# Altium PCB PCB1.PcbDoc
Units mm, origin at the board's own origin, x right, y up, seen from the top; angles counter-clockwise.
Board outline 55 x 52 mm, 6 copper layers (Top Layer, Int1 (GND), Int2 (Sign), Int3 (Sign), Int4 (PWR), Bottom Layer), stack 1.551 mm thick; 24 components, 14 nets, 48 pads, 20 vias.
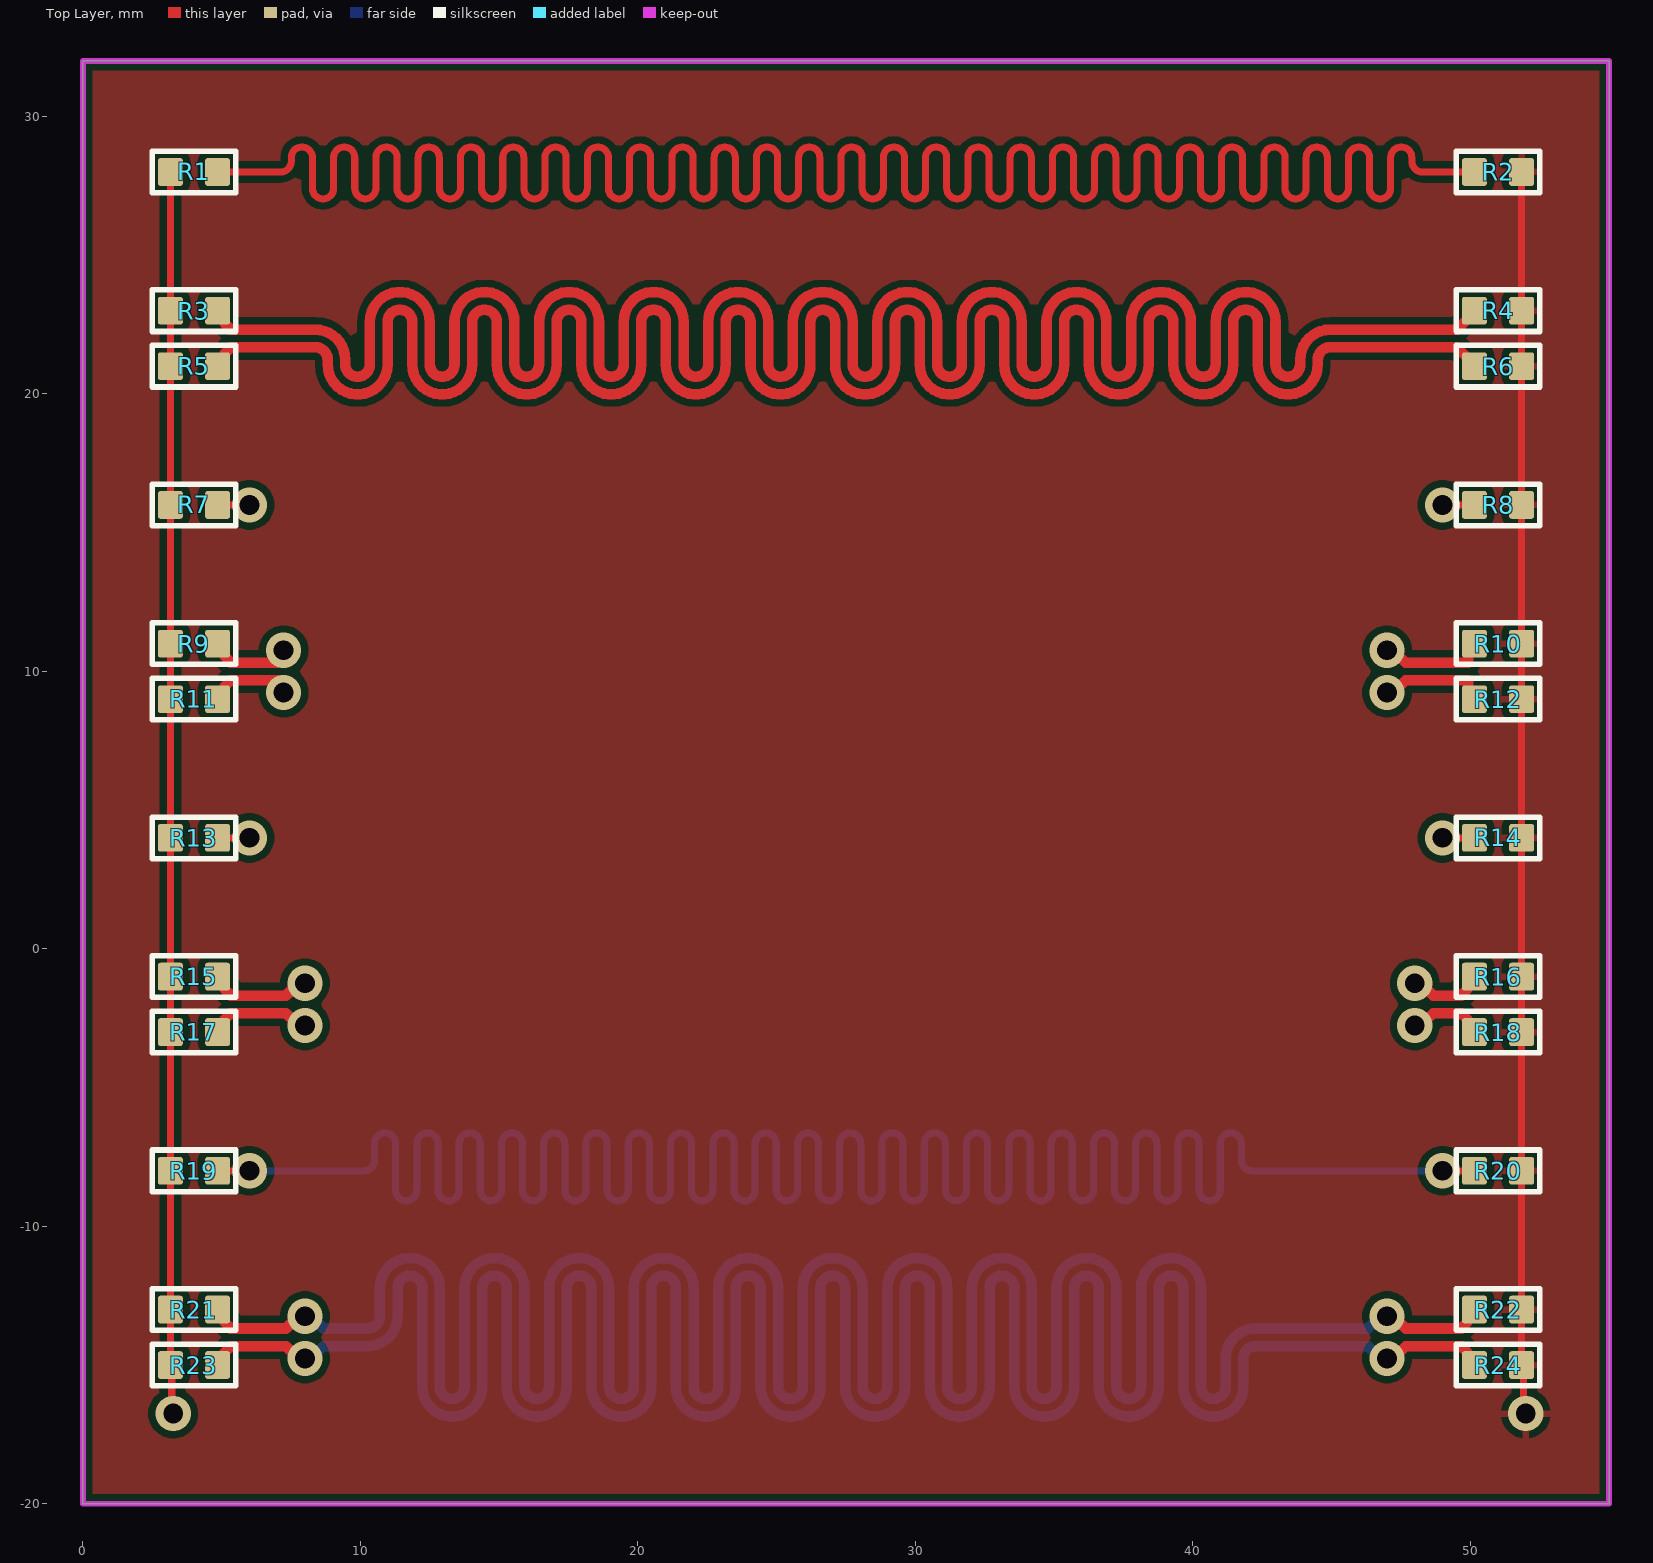
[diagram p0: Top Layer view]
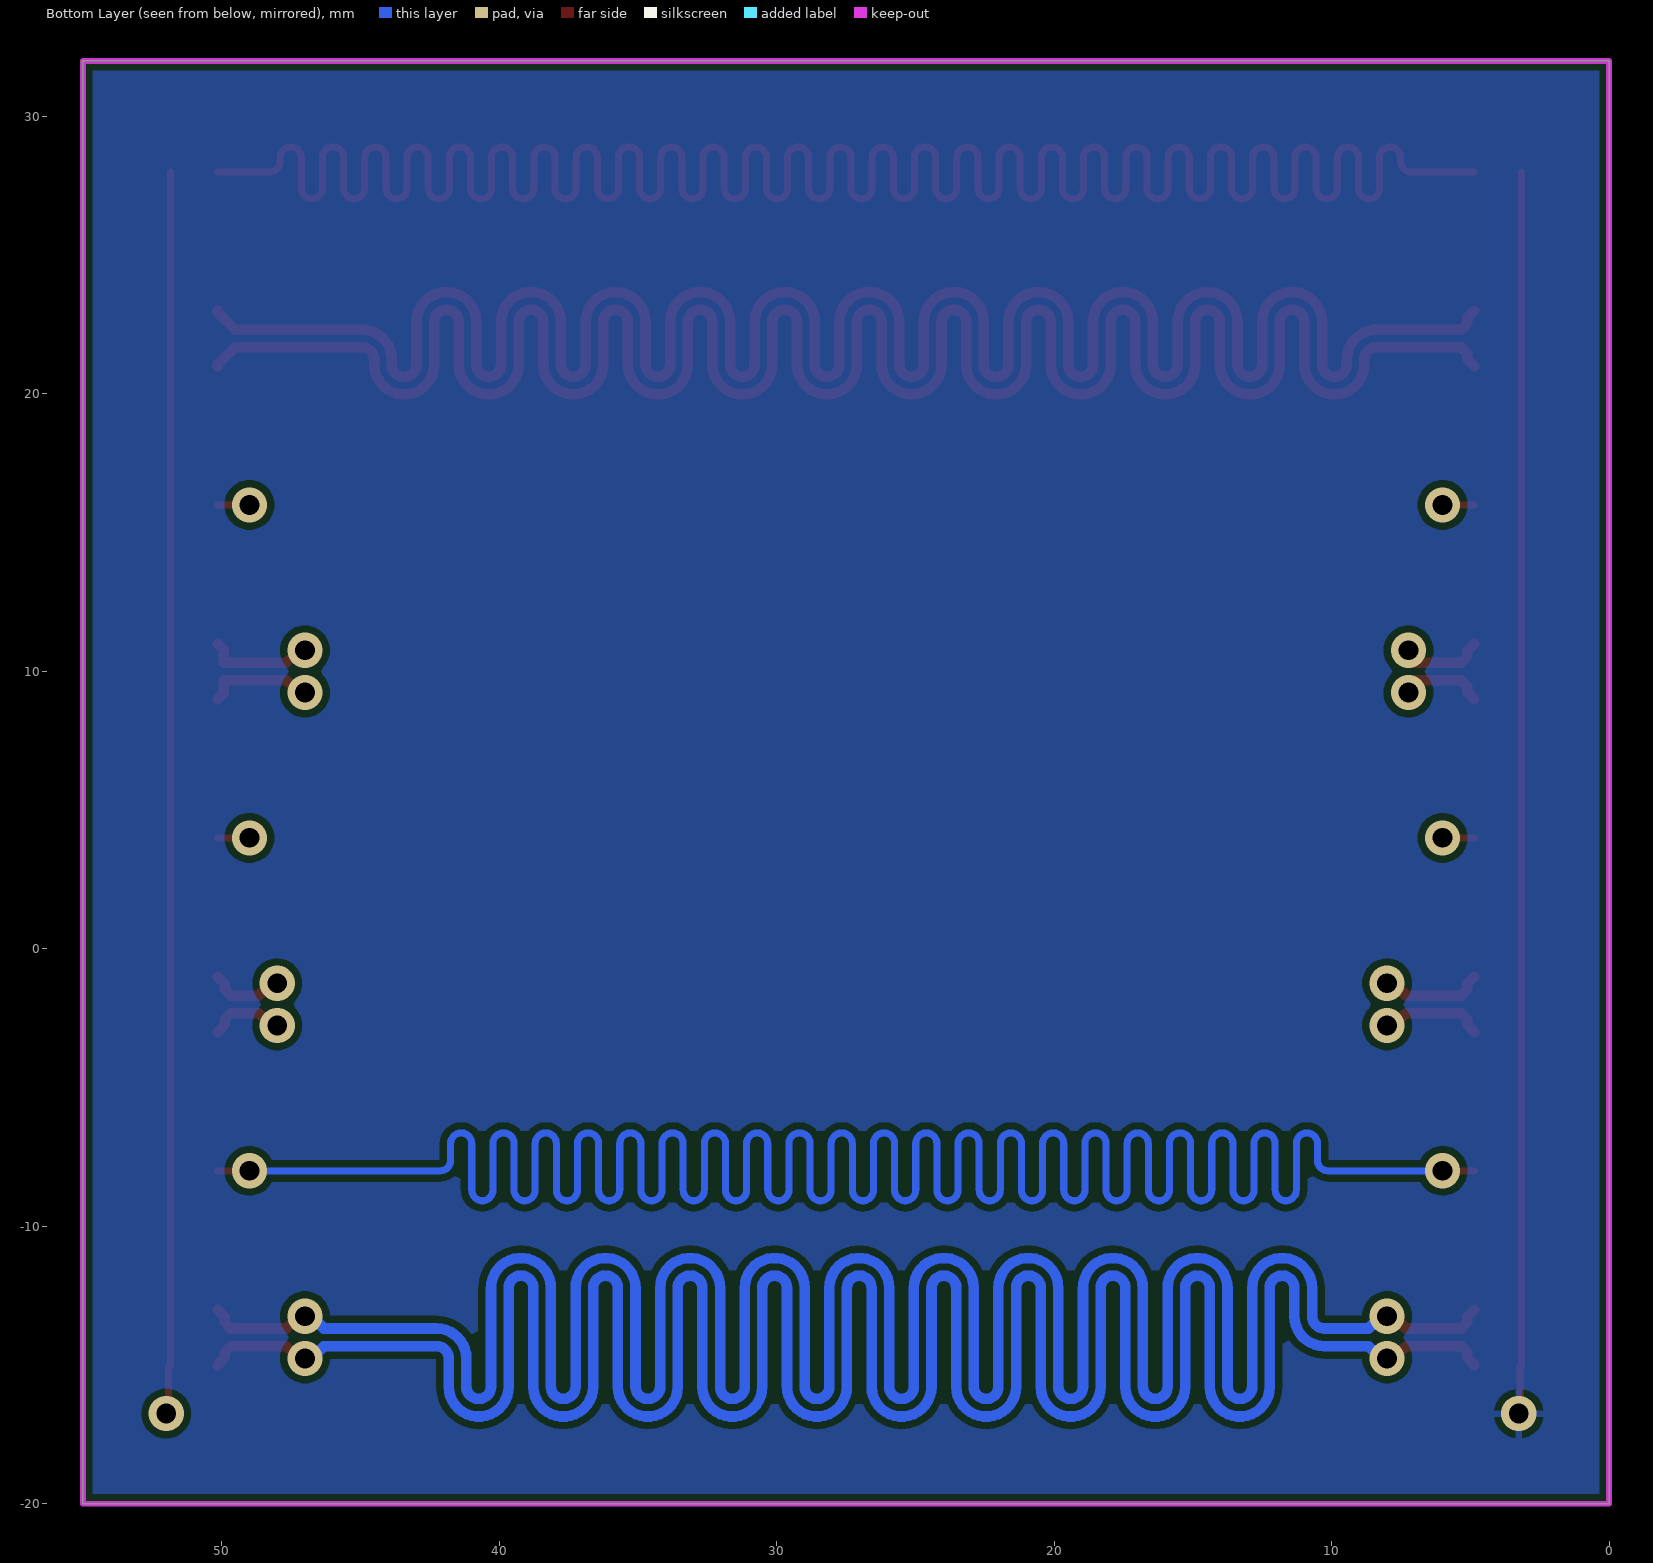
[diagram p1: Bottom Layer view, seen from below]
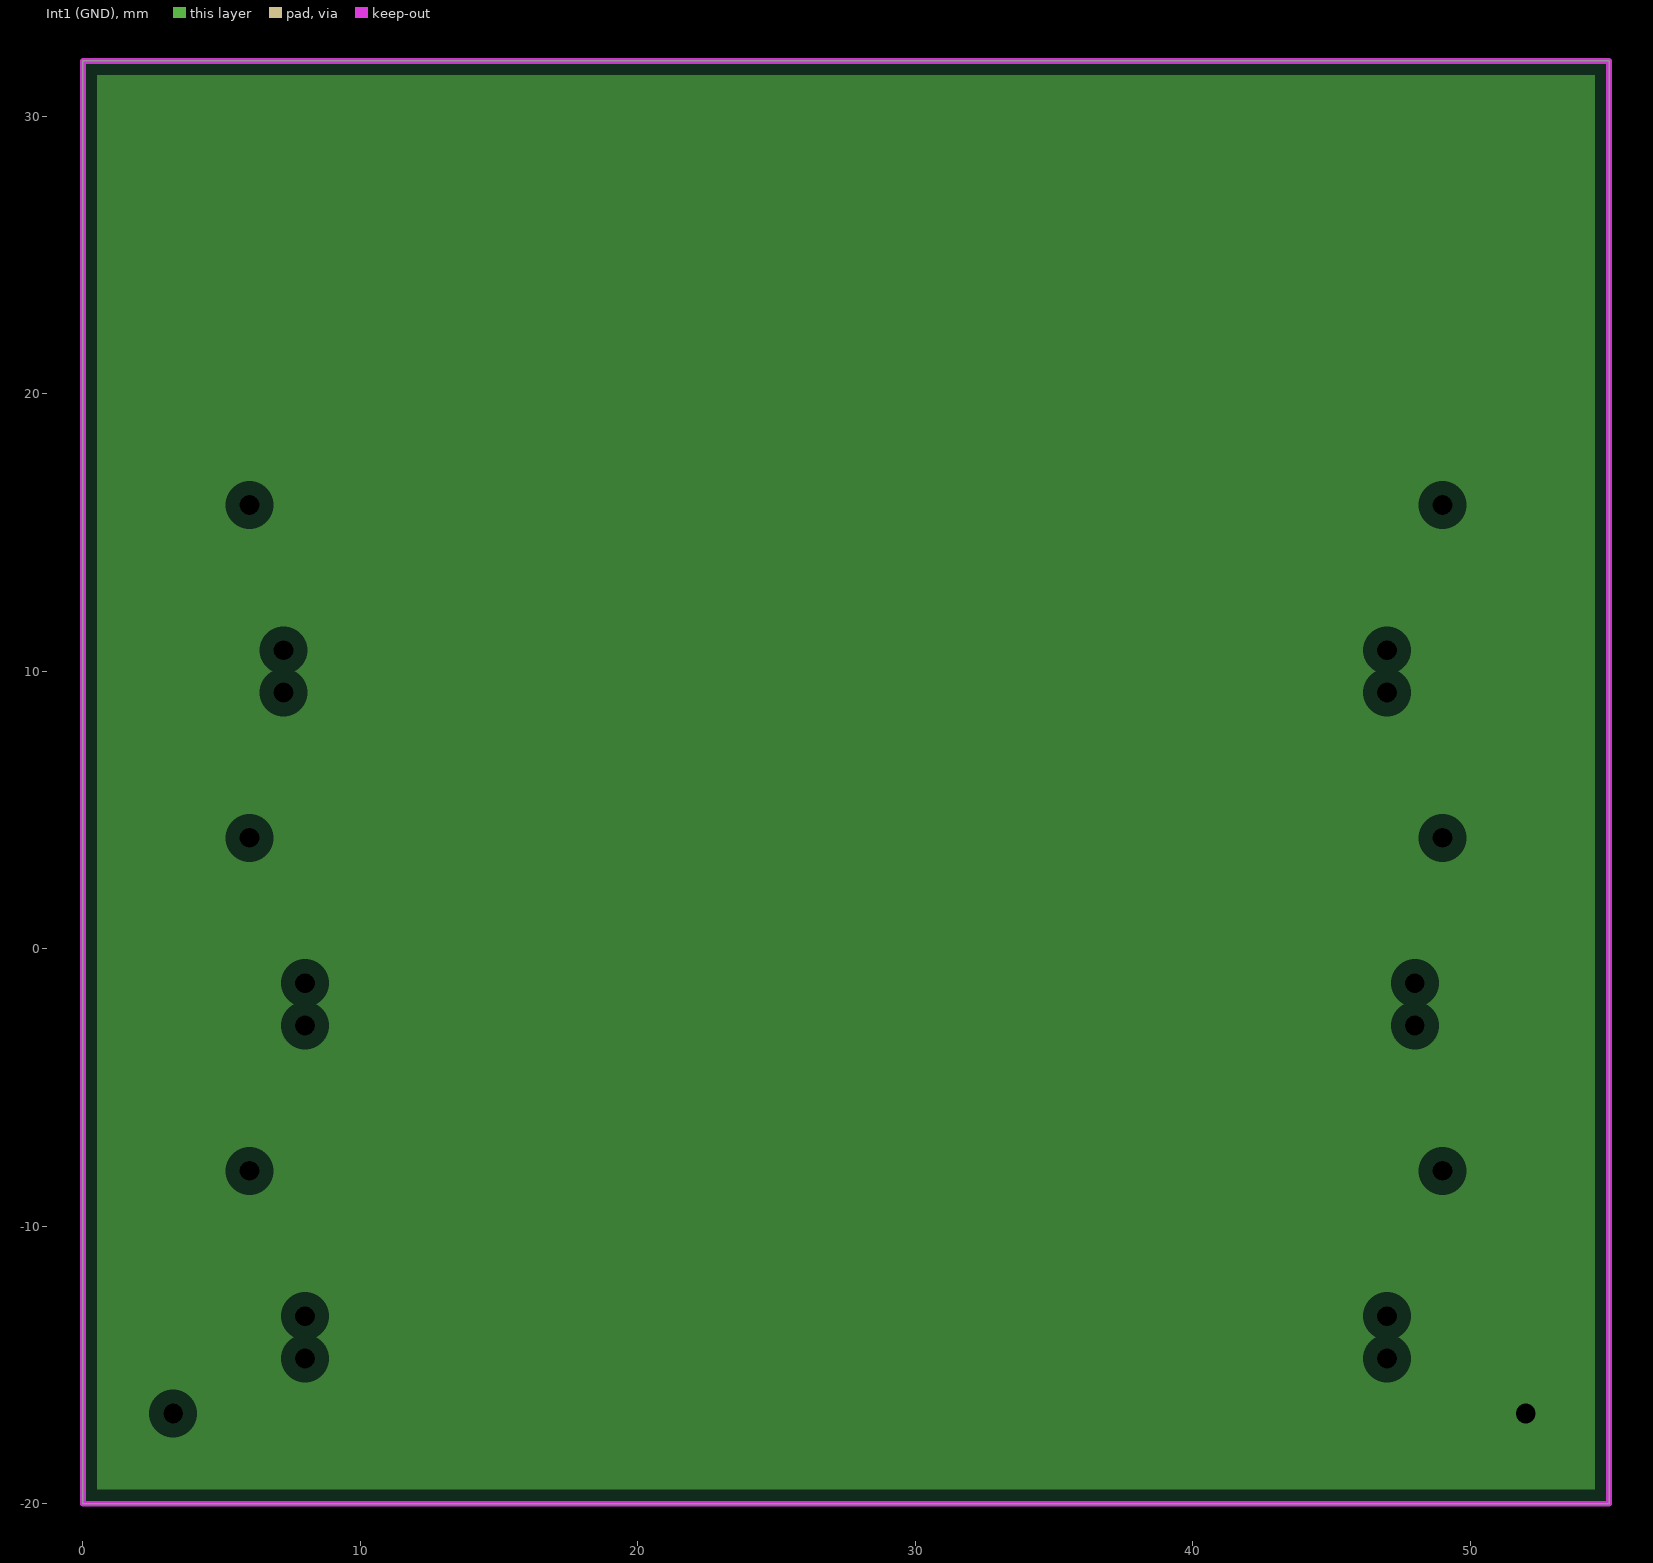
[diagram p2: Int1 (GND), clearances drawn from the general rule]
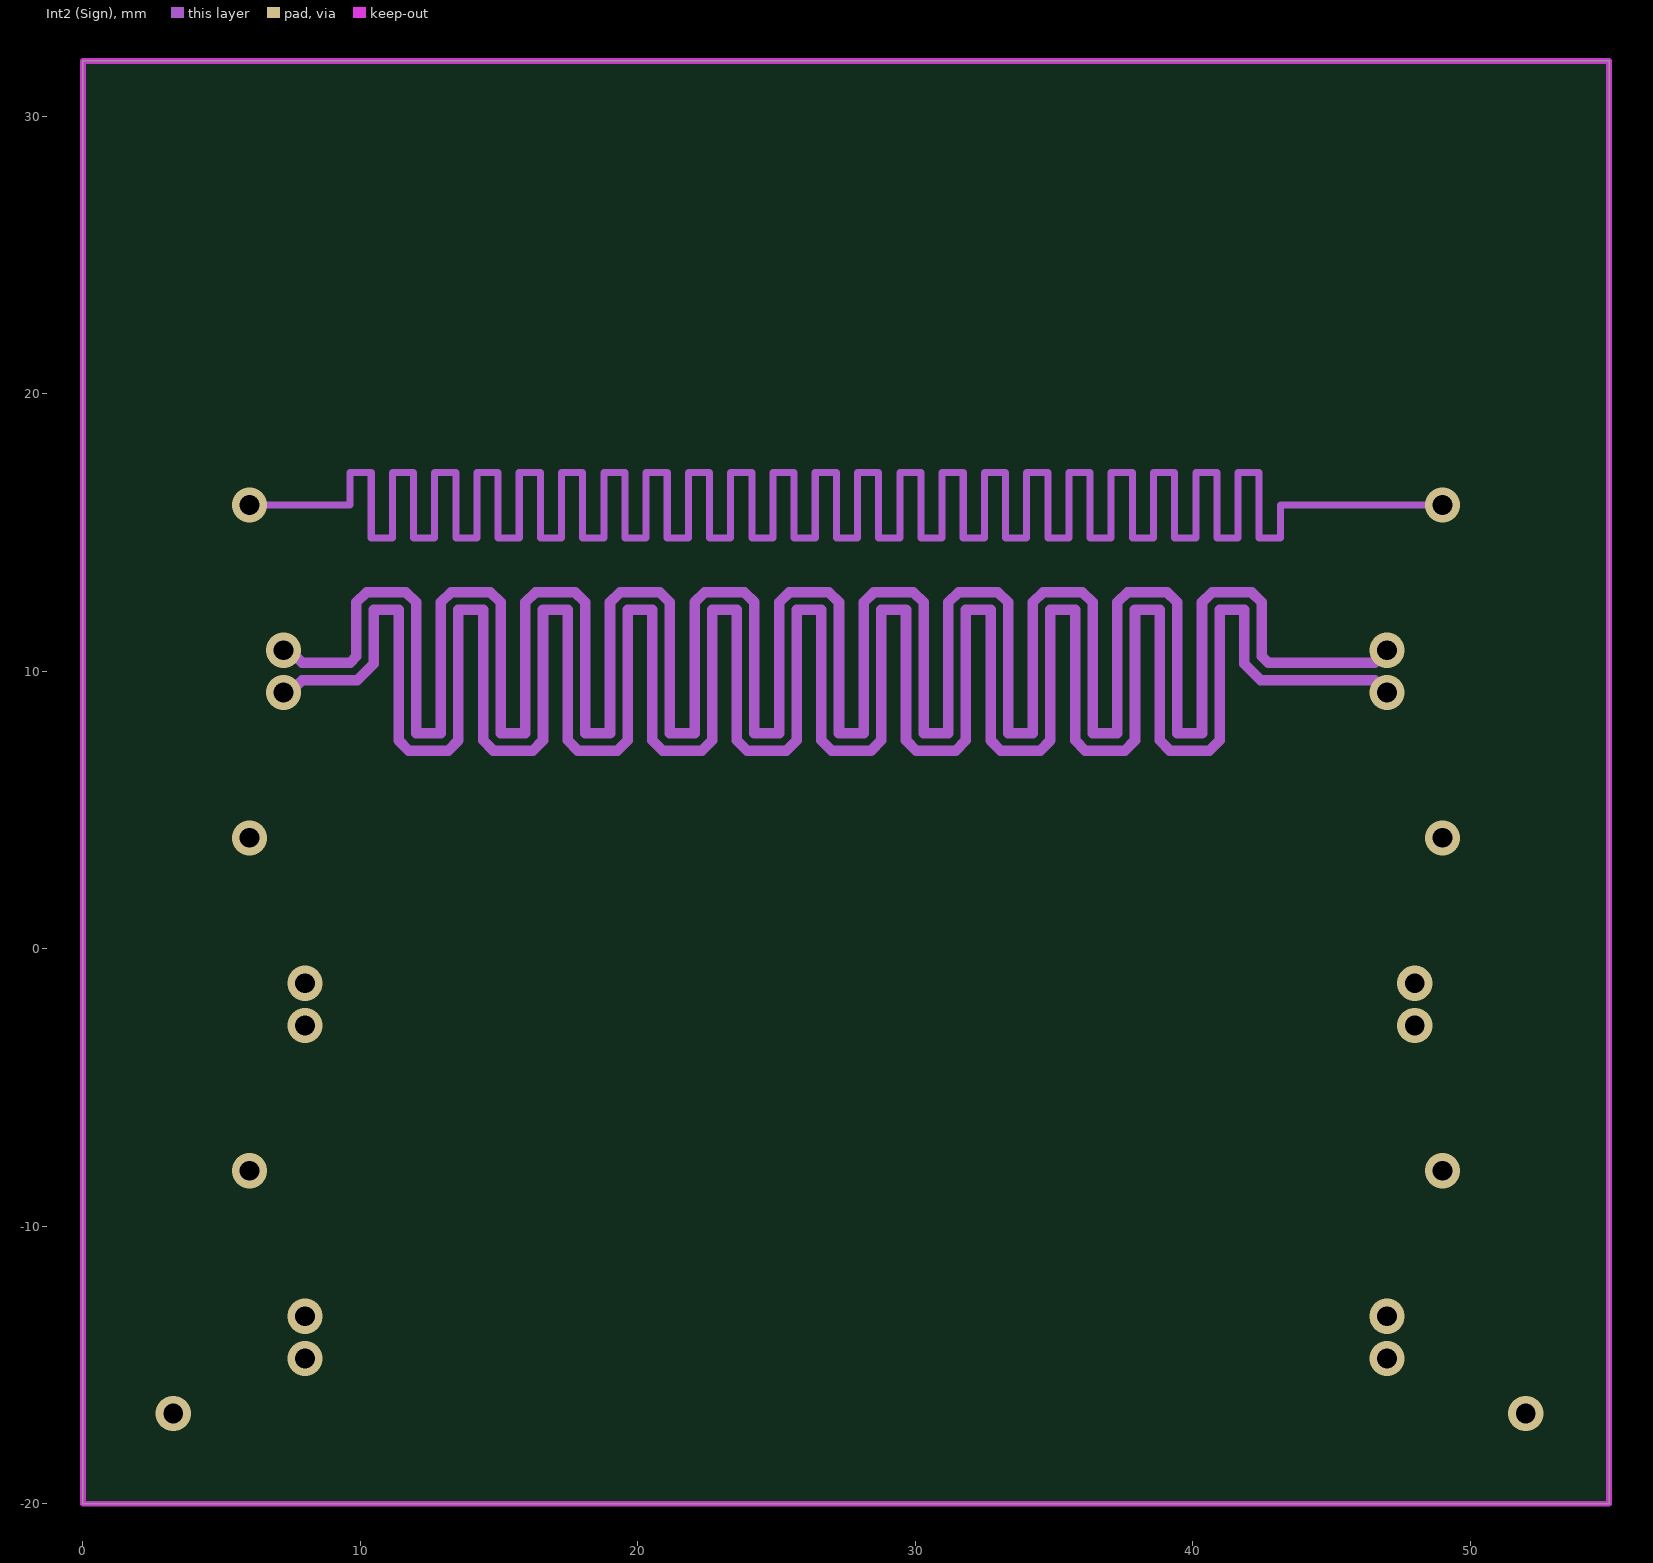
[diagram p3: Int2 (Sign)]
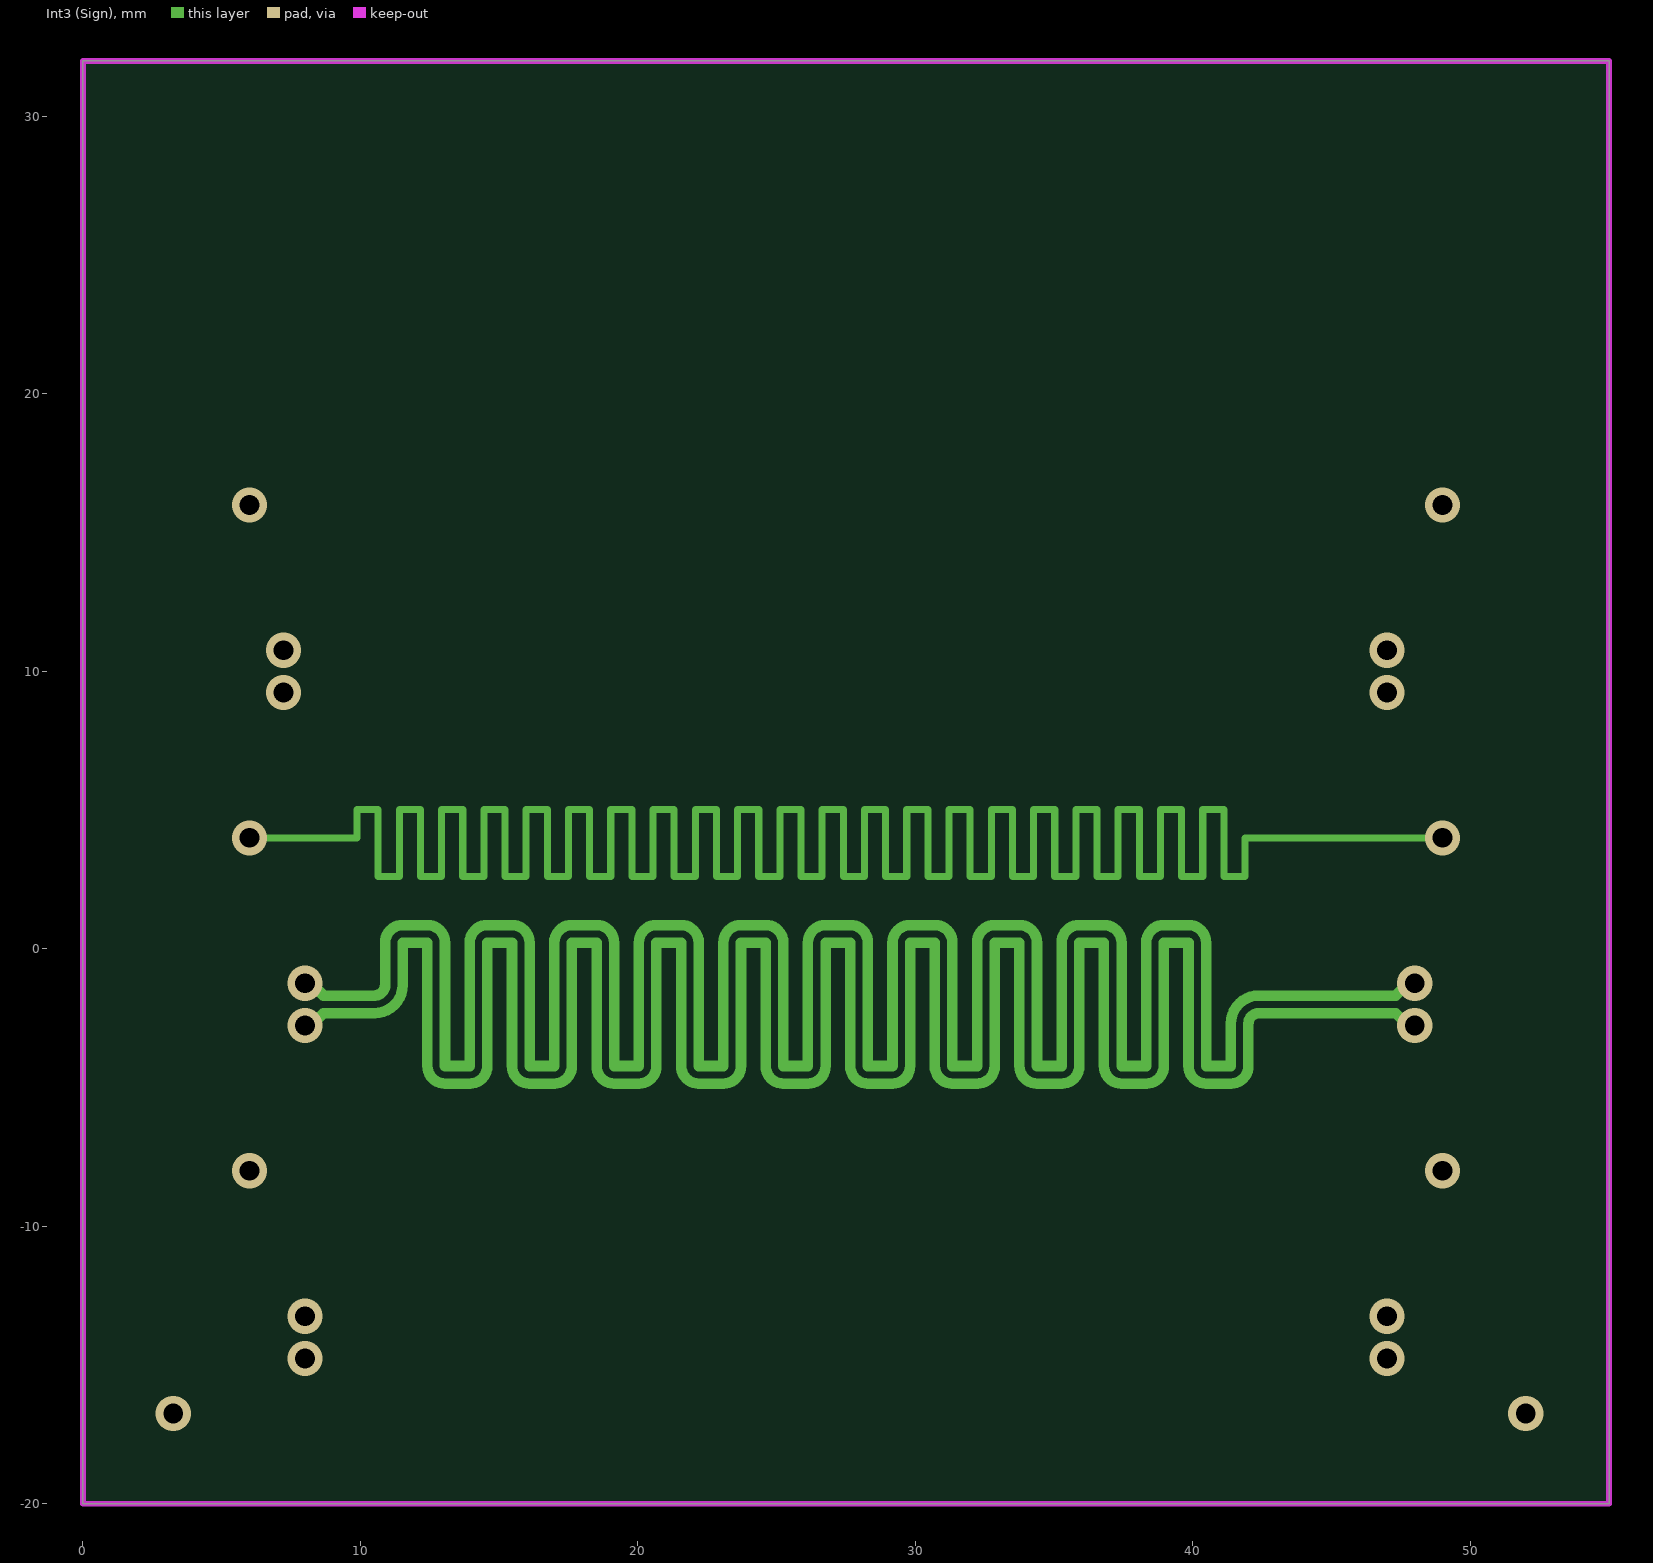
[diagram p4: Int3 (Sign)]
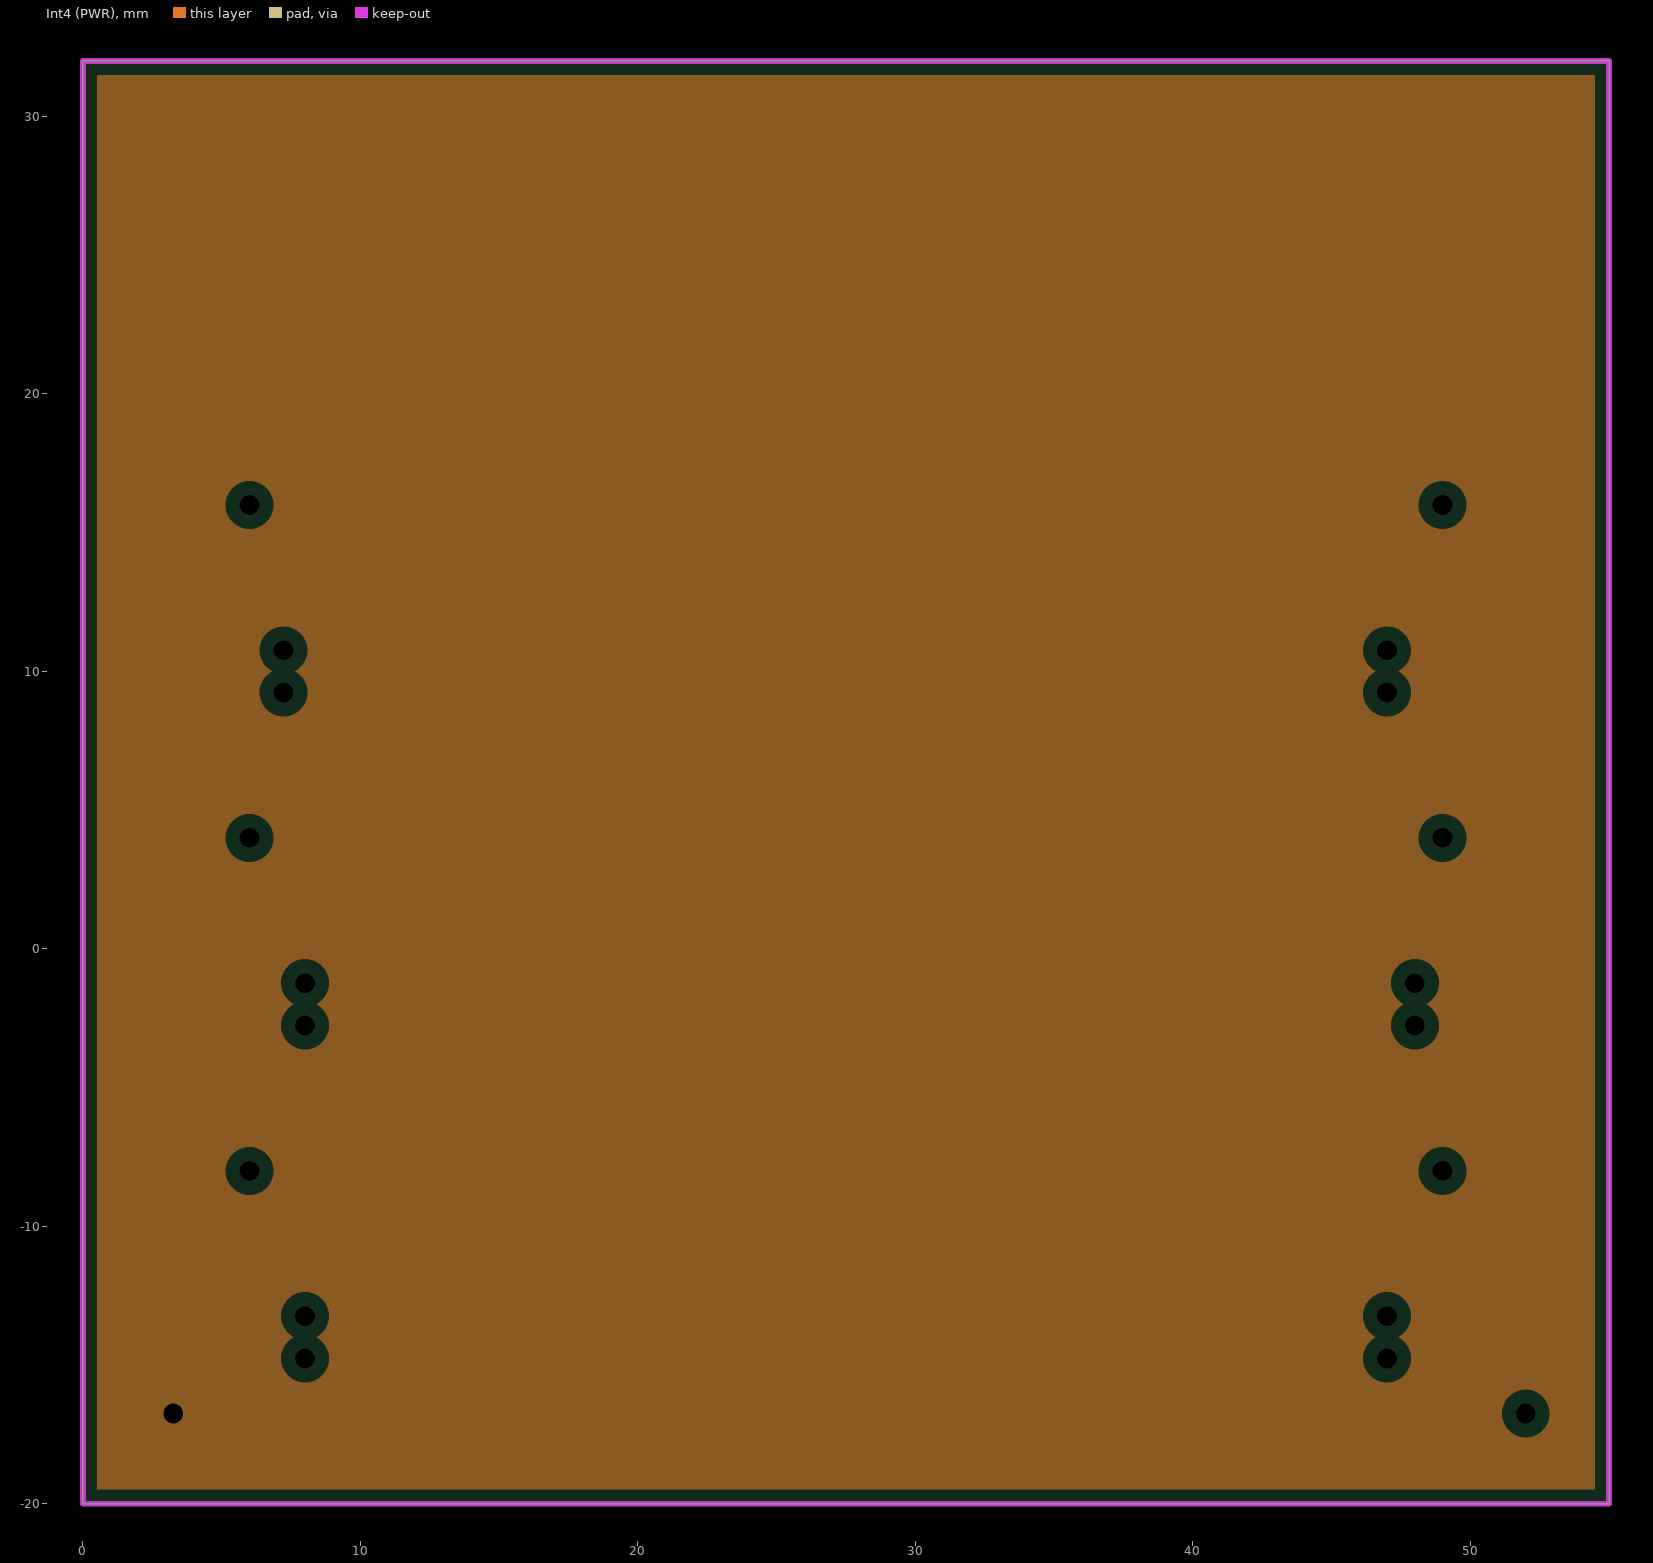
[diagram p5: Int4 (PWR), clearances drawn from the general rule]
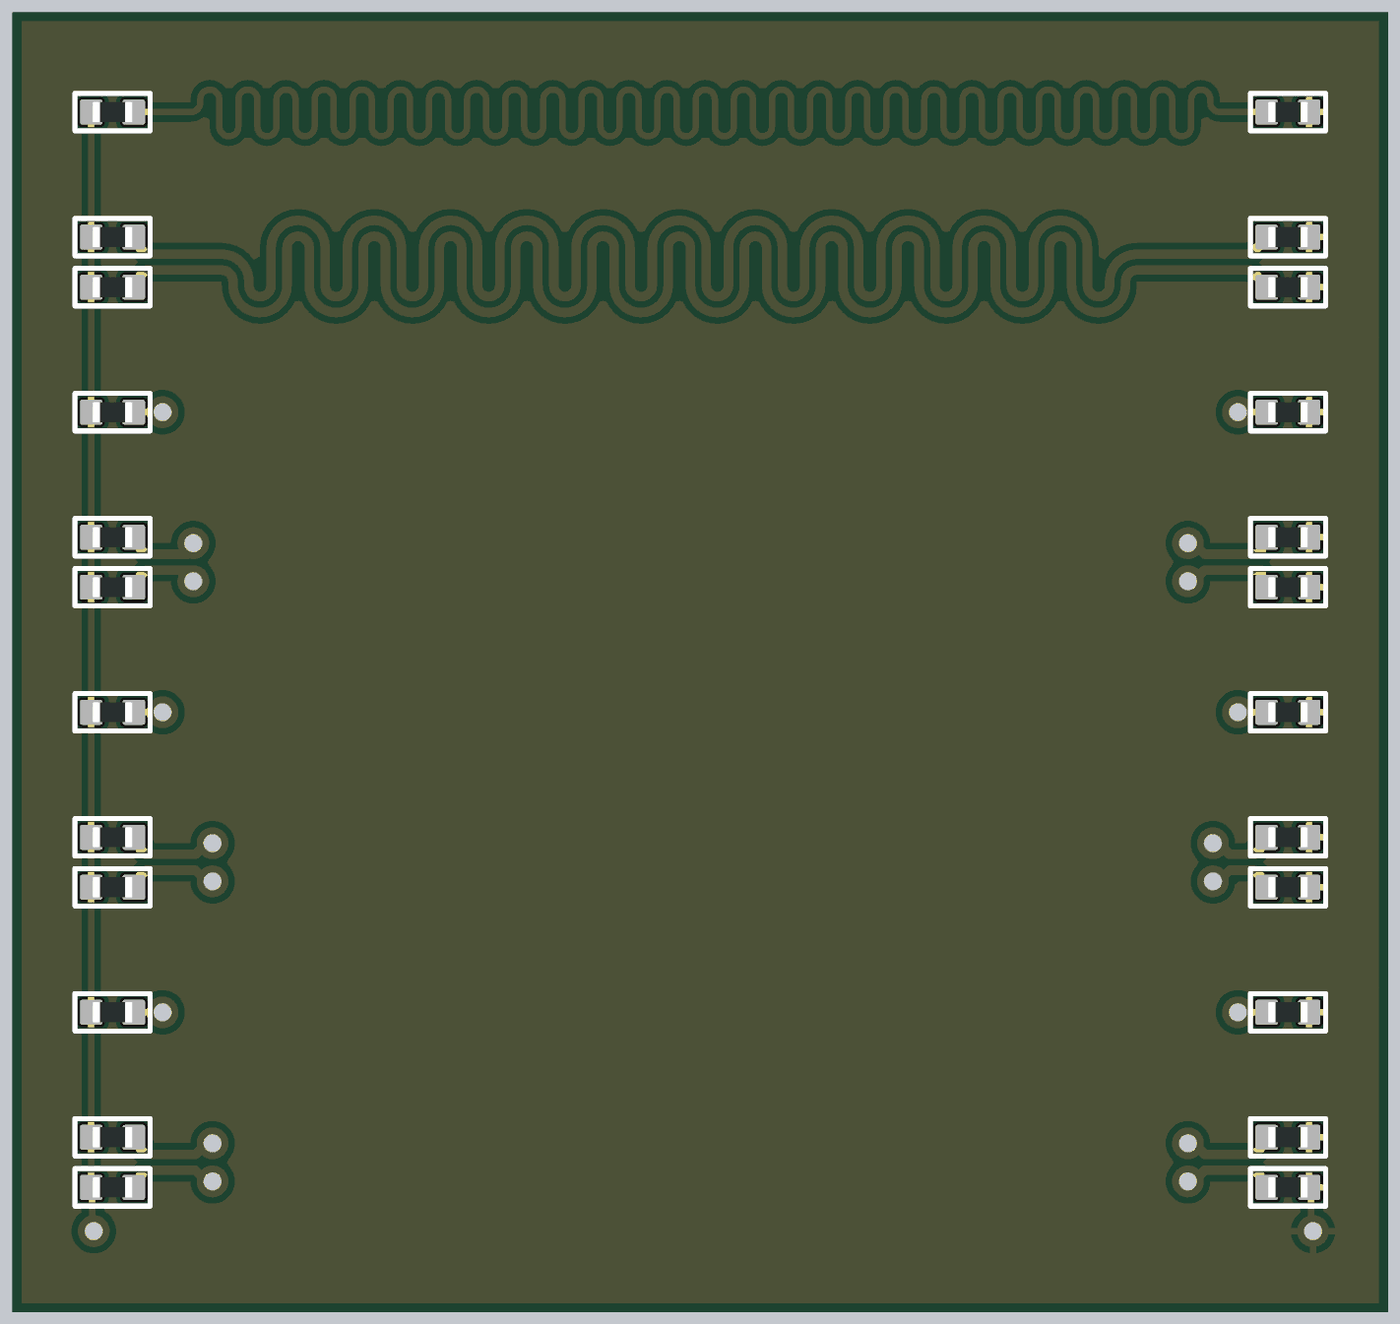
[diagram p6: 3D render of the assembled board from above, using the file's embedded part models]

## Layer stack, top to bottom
Top Solder: solder mask 0.0254, SM-001, Dk 4
Top Layer: signal copper 0.035
Dielectric 1: prepreg 0.0711, PP-006, Dk 4.1
Dielectric 2: prepreg 0.0711, PP-006, Dk 4.1
Int1 (GND): plane copper 0.035, net GND
Dielectric 3: core 0.4572, Core-035, Dk 4.7
Int2 (Sign): signal copper 0.035
Dielectric 4: prepreg 0.0711, PP-006, Dk 4.1
Dielectric 5: prepreg 0.0711, PP-006, Dk 4.1
Int3 (Sign): signal copper 0.035
Dielectric 6: core 0.4572, Core-035, Dk 4.7
Int4 (PWR): plane copper 0.035, net VCC
Dielectric 7: prepreg 0.0711, PP-006, Dk 4.1
Dielectric 8: prepreg 0.0711, PP-006, Dk 4.1
Bottom Layer: signal copper 0.035
Bottom Solder: solder mask 0.0254, SM-001, Dk 4

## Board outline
0,-20 0,32 55,32 55,-20

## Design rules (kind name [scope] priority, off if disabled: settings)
Clearance [All] p1: gap=0.254 ignorepadtopadclearanceinfootprint=FALSE
DiffPairsRouting [All] p1: maxlimit=0.254 minlimit=0.254 mostfreqgap=0.254 toplayer_minwidth=0.381 toplayer_maxwidth=0.381 toplayer_prefwidth=0.381 midlayer1_minwidth=0.381 midlayer1_maxwidth=0.381 midlayer1_prefwidth=0.381 midlayer2_minwidth=0.381 midlayer2_maxwidth=0.381 midlayer2_prefwidth=0.381 bottomlayer_minwidth=0.381 bottomlayer_maxwidth=0.381 bottomlayer_prefwidth=0.381 maxuncoupledlength=12.7
PlaneClearance [All] p1: clearance=0.508
PlaneConnect [All] p1: planeconnectstyle=Relief reliefexpansion=0.508 reliefentries=4 reliefconductorwidth=0.254 reliefairgap=0.254
PolygonConnect [All] p1: connectstyle=Relief reliefconductorwidth=0.254 reliefentries=4 polygonreliefangle="90 Angle" airgapwidth=0.254
RoutingVias [All] p1: holewidth=0.711 width=1.27 viastyle="Through Hole" minholewidth=0.711 minwidth=1.27 maxholewidth=0.711 maxwidth=1.27
SolderMaskExpansion [All] p1: expansion=0.102 istentingtop=FALSE
Width [All] p1: maxlimit=0.254 minlimit=0.254 preferedwidth=0.254
27 further rules are at their usual default settings.

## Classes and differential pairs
differential pair class 90R: Bottom_Layer_Diff Inner_Layer2_Diff Inner_Layer3_Diff Top_Layer_Diff
differential pair Top_Layer_Diff: +Top_Layer_Diff_P -Top_Layer_Diff_N
differential pair Inner_Layer3_Diff: +Inner_Layer3_Diff_P -Inner_Layer3_Diff_N
differential pair Inner_Layer2_Diff: +Inner_Layer2_Diff_P -Inner_Layer2_Diff_N
differential pair Bottom_Layer_Diff: +Bottom_Layer_Diff_P -Bottom_Layer_Diff_N

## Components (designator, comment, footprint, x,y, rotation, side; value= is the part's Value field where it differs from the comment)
R1 "RES-0603" RES-0603 4,28 r0 top value=10K
R2 "RES-0603" RES-0603 51,28 r0 top value=10K
R3 "RES-0603" RES-0603 4,23 r0 top value=10K
R4 "RES-0603" RES-0603 51,23 r0 top value=10K
R5 "RES-0603" RES-0603 4,21 r0 top value=10K
R6 "RES-0603" RES-0603 51,21 r0 top value=10K
R7 "RES-0603" RES-0603 4,16 r0 top value=10K
R8 "RES-0603" RES-0603 51,16 r0 top value=10K
R9 "RES-0603" RES-0603 4,11 r0 top value=10K
R10 "RES-0603" RES-0603 51,11 r0 top value=10K
R11 "RES-0603" RES-0603 4,9 r0 top value=10K
R12 "RES-0603" RES-0603 51,9 r0 top value=10K
R13 "RES-0603" RES-0603 4,4 r0 top value=10K
R14 "RES-0603" RES-0603 51,4 r0 top value=10K
R15 "RES-0603" RES-0603 4,-1 r0 top value=10K
R16 "RES-0603" RES-0603 51,-1 r0 top value=10K
R17 "RES-0603" RES-0603 4,-3 r0 top value=10K
R18 "RES-0603" RES-0603 51,-3 r0 top value=10K
R19 "RES-0603" RES-0603 4,-8 r0 top value=10K
R20 "RES-0603" RES-0603 51,-8 r0 top value=10K
R21 "RES-0603" RES-0603 4,-13 r0 top value=10K
R22 "RES-0603" RES-0603 51,-13 r0 top value=10K
R23 "RES-0603" RES-0603 4,-15 r0 top value=10K
R24 "RES-0603" RES-0603 51,-15 r0 top value=10K

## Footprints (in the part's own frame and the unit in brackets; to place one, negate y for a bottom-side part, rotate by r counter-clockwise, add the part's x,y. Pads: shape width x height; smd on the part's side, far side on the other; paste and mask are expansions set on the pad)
RES-0603 [mm]
  rrect20% 0.9x1 smd: 1(-0.85,0) 2(0.85,0)
  silkscreen extent -1.5,-0.75 1.5,0.75, body extent -0.8,-0.4 0.8,0.4, height 0.45

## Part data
R1 R2 R3 R4 R5 R6 R7 R8 R9 R10 R11 R12 R13 R14 R15 R16 R17 R18 R19 R20 R21 R22 R23 R24: library part Res-XR-0603, "General x Ohm 0603"

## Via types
v1: diameter 1.27, hole 0.711, Top Layer to Bottom Layer, tented both sides, 20 vias

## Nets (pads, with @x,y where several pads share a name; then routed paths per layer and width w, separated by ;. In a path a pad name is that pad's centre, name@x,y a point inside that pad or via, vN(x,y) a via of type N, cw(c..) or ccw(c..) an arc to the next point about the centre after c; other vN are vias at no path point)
Bottom_Layer_Diff_N: R23.2 R24.1 | length 134.7
  Top Layer w0.381: R23.2 5.11,-14.74 5.11,-14.541 5.333,-14.317 5.956,-14.317 7.315,-14.317 7.759,-14.762 v1(8,-14.762) ; v1(47,-14.762) 47.223,-14.762 47.668,-14.317 48.853,-14.317 49.667,-14.317 49.891,-14.541 49.891,-14.74 R24.1
  Bottom Layer w0.381: v1(8,-14.762) 8.223,-14.762 8.668,-14.317 9.75,-14.317 10.258,-14.317 ccw(c10.258,-13.238) 11.338,-13.238 11.338,-12.222 cw(c11.782,-12.222) 12.227,-12.222 12.227,-15.778 ccw(c13.306,-15.778) 14.386,-15.778 14.386,-12.222 cw(c14.83,-12.222) 15.275,-12.222 15.275,-15.778 ccw(c16.354,-15.778) 17.434,-15.778 17.434,-12.222 cw(c17.878,-12.222) 18.323,-12.222 18.323,-15.778 ccw(c19.402,-15.778) 20.482,-15.778 20.482,-12.222 cw(c20.926,-12.222) 21.371,-12.222 21.371,-15.778 ccw(c22.45,-15.778) 23.53,-15.778 23.53,-12.222 cw(c23.974,-12.222) 24.419,-12.222 24.419,-15.778 ccw(c25.498,-15.778) 26.578,-15.778 26.578,-12.222 cw(c27.022,-12.222) 27.467,-12.222 27.467,-15.778 ccw(c28.546,-15.778) 29.626,-15.778 29.626,-12.222 cw(c30.07,-12.222) 30.515,-12.222 30.515,-15.778 ccw(c31.594,-15.778) 32.674,-15.778 32.674,-12.222 cw(c33.118,-12.222) 33.563,-12.222 33.563,-15.778 ccw(c34.642,-15.778) 35.722,-15.778 35.722,-12.222 cw(c36.166,-12.222) 36.611,-12.222 36.611,-15.778 ccw(c37.69,-15.778) 38.77,-15.778 38.77,-12.222 cw(c39.214,-12.222) 39.659,-12.222 39.659,-15.778 ccw(c40.738,-15.778) 41.818,-15.778 41.818,-14.762 cw(c42.262,-14.762) 42.262,-14.317 45,-14.317 46.315,-14.317 46.759,-14.762 v1(47,-14.762)
Bottom_Layer_Diff_P: R21.2 R22.1 | length 134.7
  Top Layer w0.381: R21.2 5.11,-13.26 5.11,-13.459 5.333,-13.682 5.693,-13.682 7.315,-13.682 7.759,-13.238 v1(8,-13.238) ; v1(47,-13.238) 47.223,-13.238 47.668,-13.682 49.116,-13.682 49.667,-13.682 49.891,-13.459 49.891,-13.26 R22.1
  Bottom Layer w0.381: v1(8,-13.238) 8.223,-13.238 8.668,-13.682 9.75,-13.682 10.258,-13.682 ccw(c10.258,-13.238) 10.703,-13.238 10.703,-12.222 cw(c11.782,-12.222) 12.862,-12.222 12.862,-15.778 ccw(c13.306,-15.778) 13.751,-15.778 13.751,-12.222 cw(c14.83,-12.222) 15.91,-12.222 15.91,-15.778 ccw(c16.354,-15.778) 16.799,-15.778 16.799,-12.222 cw(c17.878,-12.222) 18.958,-12.222 18.958,-15.778 ccw(c19.402,-15.778) 19.847,-15.778 19.847,-12.222 cw(c20.926,-12.222) 22.006,-12.222 22.006,-15.778 ccw(c22.45,-15.778) 22.895,-15.778 22.895,-12.222 cw(c23.974,-12.222) 25.054,-12.222 25.054,-15.778 ccw(c25.498,-15.778) 25.943,-15.778 25.943,-12.222 cw(c27.022,-12.222) 28.102,-12.222 28.102,-15.778 ccw(c28.546,-15.778) 28.991,-15.778 28.991,-12.222 cw(c30.07,-12.222) 31.15,-12.222 31.15,-15.778 ccw(c31.594,-15.778) 32.039,-15.778 32.039,-12.222 cw(c33.118,-12.222) 34.198,-12.222 34.198,-15.778 ccw(c34.642,-15.778) 35.087,-15.778 35.087,-12.222 cw(c36.166,-12.222) 37.246,-12.222 37.246,-15.778 ccw(c37.69,-15.778) 38.135,-15.778 38.135,-12.222 cw(c39.214,-12.222) 40.294,-12.222 40.294,-15.778 ccw(c40.738,-15.778) 41.183,-15.778 41.183,-14.762 cw(c42.262,-14.762) 42.262,-13.682 45,-13.682 46.315,-13.682 46.759,-13.238 v1(47,-13.238)
Bottom_Layer_Single: R19.2 R20.1 | length 132.1
  Top Layer w0.254: R19.2 v1(6,-8) ; v1(49,-8) R20.1
  Bottom Layer w0.254: v1(6,-8) 10,-8 10.127,-8 ccw(c10.127,-7.619) 10.508,-7.619 10.508,-7.015 cw(c10.889,-7.015) 11.27,-7.015 11.27,-8.698 ccw(c11.651,-8.698) 12.032,-8.698 12.032,-7.015 cw(c12.413,-7.015) 12.794,-7.015 12.794,-8.698 ccw(c13.175,-8.698) 13.556,-8.698 13.556,-7.015 cw(c13.937,-7.015) 14.318,-7.015 14.318,-8.698 ccw(c14.699,-8.698) 15.08,-8.698 15.08,-7.015 cw(c15.461,-7.015) 15.842,-7.015 15.842,-8.698 ccw(c16.223,-8.698) 16.604,-8.698 16.604,-7.015 cw(c16.985,-7.015) 17.366,-7.015 17.366,-8.698 ccw(c17.747,-8.698) 18.128,-8.698 18.128,-7.015 cw(c18.509,-7.015) 18.89,-7.015 18.89,-8.698 ccw(c19.271,-8.698) 19.652,-8.698 19.652,-7.015 cw(c20.033,-7.015) 20.414,-7.015 20.414,-8.698 ccw(c20.795,-8.698) 21.176,-8.698 21.176,-7.015 cw(c21.557,-7.015) 21.938,-7.015 21.938,-8.698 ccw(c22.319,-8.698) 22.7,-8.698 22.7,-7.015 cw(c23.081,-7.015) 23.462,-7.015 23.462,-8.698 ccw(c23.843,-8.698) 24.224,-8.698 24.224,-7.015 cw(c24.605,-7.015) 24.986,-7.015 24.986,-8.698 ccw(c25.367,-8.698) 25.748,-8.698 25.748,-7.015 cw(c26.129,-7.015) 26.51,-7.015 26.51,-8.698 ccw(c26.891,-8.698) 27.272,-8.698 27.272,-7.015 cw(c27.653,-7.015) 28.034,-7.015 28.034,-8.698 ccw(c28.415,-8.698) 28.796,-8.698 28.796,-7.015 cw(c29.177,-7.015) 29.558,-7.015 29.558,-8.698 ccw(c29.939,-8.698) 30.32,-8.698 30.32,-7.015 cw(c30.701,-7.015) 31.082,-7.015 31.082,-8.698 ccw(c31.463,-8.698) 31.844,-8.698 31.844,-7.015 cw(c32.225,-7.015) 32.606,-7.015 32.606,-8.698 ccw(c32.987,-8.698) 33.368,-8.698 33.368,-7.015 cw(c33.749,-7.015) 34.13,-7.015 34.13,-8.698 ccw(c34.511,-8.698) 34.892,-8.698 34.892,-7.015 cw(c35.273,-7.015) 35.654,-7.015 35.654,-8.698 ccw(c36.035,-8.698) 36.416,-8.698 36.416,-7.015 cw(c36.797,-7.015) 37.178,-7.015 37.178,-8.698 ccw(c37.559,-8.698) 37.94,-8.698 37.94,-7.015 cw(c38.321,-7.015) 38.702,-7.015 38.702,-8.698 ccw(c39.083,-8.698) 39.464,-8.698 39.464,-7.015 cw(c39.845,-7.015) 40.226,-7.015 40.226,-8.698 ccw(c40.607,-8.698) 40.988,-8.698 40.988,-7.015 cw(c41.369,-7.015) 41.75,-7.015 41.75,-7.619 ccw(c42.131,-7.619) 42.131,-8 43.25,-8 v1(49,-8)
GND: R2.2 R4.2 R6.2 R8.2 R10.2 R12.2 R14.2 R16.2 R18.2 R20.2 R22.2 R24.2 | length 44.8
  Top Layer w0.254: R2.2 R4.2 R6.2 R8.2 R10.2 R12.2 R14.2 R16.2 R18.2 R20.2 R22.2 R24.2 51.925,-15.075 51.925,-16.675 v1(52,-16.75)
Inner_Layer2_Diff_N: R11.2 R12.1 | length 148.7
  Top Layer w0.381: R11.2 5.11,9.26 5.11,9.459 5.333,9.683 7,9.683 7.229,9.453 v1(7.229,9.238) ; v1(47,9.238) 47.223,9.238 47.668,9.683 49.927,9.683 49.927,9.223 R12.1
  Int2 (Sign) w0.381: v1(7.229,9.238) 7.452,9.238 7.897,9.683 9.25,9.683 9.89,9.683 10.485,10.278 10.485,12.223 11.374,12.223 11.374,7.514 11.746,7.143 13.161,7.143 13.533,7.514 13.533,12.223 14.422,12.223 14.422,7.514 14.794,7.143 16.209,7.143 16.581,7.514 16.581,12.223 17.47,12.223 17.47,7.514 17.842,7.143 19.257,7.143 19.629,7.514 19.629,12.223 20.518,12.223 20.518,7.514 20.89,7.143 22.305,7.143 22.677,7.514 22.677,12.223 23.566,12.223 23.566,7.514 23.938,7.143 25.353,7.143 25.725,7.514 25.725,12.223 26.614,12.223 26.614,7.514 26.986,7.143 28.401,7.143 28.773,7.514 28.773,12.223 29.662,12.223 29.662,7.514 30.034,7.143 31.449,7.143 31.821,7.514 31.821,12.223 32.71,12.223 32.71,7.514 33.082,7.143 34.497,7.143 34.869,7.514 34.869,12.223 35.758,12.223 35.758,7.514 36.13,7.143 37.545,7.143 37.917,7.514 37.917,12.223 38.806,12.223 38.806,7.514 39.178,7.143 40.593,7.143 40.965,7.514 40.965,12.223 41.854,12.223 41.854,10.278 42.449,9.683 44.5,9.683 46.556,9.683 v1(47,9.238)
Inner_Layer2_Diff_P: R9.2 R10.1 | length 148.7
  Top Layer w0.381: R9.2 5.11,10.74 5.11,10.541 5.333,10.318 7,10.318 7.229,10.547 v1(7.229,10.762) ; v1(47,10.762) 47.223,10.762 47.668,10.318 49.927,10.318 49.927,10.777 R10.1
  Int2 (Sign) w0.381: v1(7.229,10.762) 7.452,10.762 7.897,10.318 9.25,10.318 9.627,10.318 9.85,10.541 9.85,12.486 10.222,12.858 11.637,12.858 12.009,12.486 12.009,7.778 12.898,7.778 12.898,12.486 13.27,12.858 14.685,12.858 15.057,12.486 15.057,7.778 15.946,7.778 15.946,12.486 16.318,12.858 17.733,12.858 18.105,12.486 18.105,7.778 18.994,7.778 18.994,12.486 19.366,12.858 20.781,12.858 21.153,12.486 21.153,7.778 22.042,7.778 22.042,12.486 22.414,12.858 23.829,12.858 24.201,12.486 24.201,7.778 25.09,7.778 25.09,12.486 25.462,12.858 26.877,12.858 27.249,12.486 27.249,7.778 28.138,7.778 28.138,12.486 28.51,12.858 29.925,12.858 30.297,12.486 30.297,7.778 31.186,7.778 31.186,12.486 31.558,12.858 32.973,12.858 33.345,12.486 33.345,7.778 34.234,7.778 34.234,12.486 34.606,12.858 36.021,12.858 36.393,12.486 36.393,7.778 37.282,7.778 37.282,12.486 37.654,12.858 39.069,12.858 39.441,12.486 39.441,7.778 40.33,7.778 40.33,12.486 40.702,12.858 42.117,12.858 42.489,12.486 42.489,10.541 42.712,10.318 44.5,10.318 46.556,10.318 v1(47,10.762)
Inner_Layer2_Single: R7.2 R8.1 | length 149.7
  Top Layer w0.254: R7.2 v1(6,16) ; v1(49,16) R8.1
  Int2 (Sign) w0.254: v1(6,16) 9.5,16 9.627,16 9.627,17.172 10.389,17.172 10.389,14.8 11.151,14.8 11.151,17.172 11.913,17.172 11.913,14.8 12.675,14.8 12.675,17.172 13.437,17.172 13.437,14.8 14.199,14.8 14.199,17.172 14.961,17.172 14.961,14.8 15.723,14.8 15.723,17.172 16.485,17.172 16.485,14.8 17.247,14.8 17.247,17.172 18.009,17.172 18.009,14.8 18.771,14.8 18.771,17.172 19.533,17.172 19.533,14.8 20.295,14.8 20.295,17.172 21.057,17.172 21.057,14.8 21.819,14.8 21.819,17.172 22.581,17.172 22.581,14.8 23.343,14.8 23.343,17.172 24.105,17.172 24.105,14.8 24.867,14.8 24.867,17.172 25.629,17.172 25.629,14.8 26.391,14.8 26.391,17.172 27.153,17.172 27.153,14.8 27.915,14.8 27.915,17.172 28.677,17.172 28.677,14.8 29.439,14.8 29.439,17.172 30.201,17.172 30.201,14.8 30.963,14.8 30.963,17.172 31.725,17.172 31.725,14.8 32.487,14.8 32.487,17.172 33.249,17.172 33.249,14.8 34.011,14.8 34.011,17.172 34.773,17.172 34.773,14.8 35.535,14.8 35.535,17.172 36.297,17.172 36.297,14.8 37.059,14.8 37.059,17.172 37.821,17.172 37.821,14.8 38.583,14.8 38.583,17.172 39.345,17.172 39.345,14.8 40.107,14.8 40.107,17.172 40.869,17.172 40.869,14.8 41.631,14.8 41.631,17.172 42.393,17.172 42.393,14.8 43.155,14.8 43.155,16 43.75,16 v1(49,16)
Inner_Layer3_Diff_N: R17.2 R18.1 | length 142.4
  Top Layer w0.381: R17.2 5.11,-2.74 5.11,-2.541 5.333,-2.318 5.956,-2.318 7.315,-2.317 7.759,-2.762 v1(8,-2.762) ; v1(48,-2.762) 48.223,-2.762 48.668,-2.317 49.044,-2.317 49.667,-2.318 49.891,-2.541 49.891,-2.74 R18.1
  Int3 (Sign) w0.381: v1(8,-2.762) 8.223,-2.762 8.668,-2.317 10,-2.317 10.508,-2.317 ccw(c10.508,-1.301) 11.524,-1.301 11.524,0.223 12.413,0.223 12.413,-4.222 ccw(c13.048,-4.222) 13.048,-4.857 13.937,-4.857 ccw(c13.937,-4.222) 14.572,-4.222 14.572,0.223 15.461,0.223 15.461,-4.222 ccw(c16.096,-4.222) 16.096,-4.857 16.985,-4.857 ccw(c16.985,-4.222) 17.62,-4.222 17.62,0.223 18.509,0.223 18.509,-4.222 ccw(c19.144,-4.222) 19.144,-4.857 20.033,-4.857 ccw(c20.033,-4.222) 20.668,-4.222 20.668,0.223 21.557,0.223 21.557,-4.222 ccw(c22.192,-4.222) 22.192,-4.857 23.081,-4.857 ccw(c23.081,-4.222) 23.716,-4.222 23.716,0.223 24.605,0.223 24.605,-4.222 ccw(c25.24,-4.222) 25.24,-4.857 26.129,-4.857 ccw(c26.129,-4.222) 26.764,-4.222 26.764,0.223 27.653,0.223 27.653,-4.222 ccw(c28.288,-4.222) 28.288,-4.857 29.177,-4.857 ccw(c29.177,-4.222) 29.812,-4.222 29.812,0.223 30.701,0.223 30.701,-4.222 ccw(c31.336,-4.222) 31.336,-4.857 32.225,-4.857 ccw(c32.225,-4.222) 32.86,-4.222 32.86,0.223 33.749,0.223 33.749,-4.222 ccw(c34.384,-4.222) 34.384,-4.857 35.273,-4.857 ccw(c35.273,-4.222) 35.908,-4.222 35.908,0.223 36.797,0.223 36.797,-4.222 ccw(c37.432,-4.222) 37.432,-4.857 38.321,-4.857 ccw(c38.321,-4.222) 38.956,-4.222 38.956,0.223 39.845,0.223 39.845,-4.222 ccw(c40.48,-4.222) 40.48,-4.857 41.369,-4.857 ccw(c41.369,-4.222) 42.004,-4.222 42.004,-2.698 cw(c42.385,-2.698) 42.385,-2.317 44.75,-2.317 47.315,-2.317 47.759,-2.762 v1(48,-2.762)
Inner_Layer3_Diff_P: R15.2 R16.1 | length 142.4
  Top Layer w0.381: R15.2 5.11,-1.26 5.11,-1.459 5.333,-1.683 5.693,-1.683 7.315,-1.682 7.759,-1.238 v1(8,-1.238) ; v1(48,-1.238) 48.223,-1.238 48.668,-1.682 49.307,-1.682 49.667,-1.683 49.891,-1.459 49.891,-1.26 R16.1
  Int3 (Sign) w0.381: v1(8,-1.238) 8.223,-1.238 8.668,-1.682 10,-1.682 10.508,-1.682 ccw(c10.508,-1.301) 10.889,-1.301 10.889,0.223 cw(c11.524,0.223) 11.524,0.858 12.413,0.858 cw(c12.413,0.223) 13.048,0.223 13.048,-4.222 13.937,-4.222 13.937,0.223 cw(c14.572,0.223) 14.572,0.858 15.461,0.858 cw(c15.461,0.223) 16.096,0.223 16.096,-4.222 16.985,-4.222 16.985,0.223 cw(c17.62,0.223) 17.62,0.858 18.509,0.858 cw(c18.509,0.223) 19.144,0.223 19.144,-4.222 20.033,-4.222 20.033,0.223 cw(c20.668,0.223) 20.668,0.858 21.557,0.858 cw(c21.557,0.223) 22.192,0.223 22.192,-4.222 23.081,-4.222 23.081,0.223 cw(c23.716,0.223) 23.716,0.858 24.605,0.858 cw(c24.605,0.223) 25.24,0.223 25.24,-4.222 26.129,-4.222 26.129,0.223 cw(c26.764,0.223) 26.764,0.858 27.653,0.858 cw(c27.653,0.223) 28.288,0.223 28.288,-4.222 29.177,-4.222 29.177,0.223 cw(c29.812,0.223) 29.812,0.858 30.701,0.858 cw(c30.701,0.223) 31.336,0.223 31.336,-4.222 32.225,-4.222 32.225,0.223 cw(c32.86,0.223) 32.86,0.858 33.749,0.858 cw(c33.749,0.223) 34.384,0.223 34.384,-4.222 35.273,-4.222 35.273,0.223 cw(c35.908,0.223) 35.908,0.858 36.797,0.858 cw(c36.797,0.223) 37.432,0.223 37.432,-4.222 38.321,-4.222 38.321,0.223 cw(c38.956,0.223) 38.956,0.858 39.845,0.858 cw(c39.845,0.223) 40.48,0.223 40.48,-4.222 41.369,-4.222 41.369,-2.698 cw(c42.385,-2.698) 42.385,-1.682 44.75,-1.682 47.315,-1.682 47.759,-1.238 v1(48,-1.238)
Inner_Layer3_Single: R13.2 R14.1 | length 147
  Top Layer w0.254: R13.2 v1(6,4) ; v1(49,4) R14.1
  Int3 (Sign) w0.254: v1(6,4) 9.75,4 9.877,4 9.877,5.029 10.639,5.029 10.639,2.607 11.401,2.607 11.401,5.029 12.163,5.029 12.163,2.607 12.925,2.607 12.925,5.029 13.687,5.029 13.687,2.607 14.449,2.607 14.449,5.029 15.211,5.029 15.211,2.607 15.973,2.607 15.973,5.029 16.735,5.029 16.735,2.607 17.497,2.607 17.497,5.029 18.259,5.029 18.259,2.607 19.021,2.607 19.021,5.029 19.783,5.029 19.783,2.607 20.545,2.607 20.545,5.029 21.307,5.029 21.307,2.607 22.069,2.607 22.069,5.029 22.831,5.029 22.831,2.607 23.593,2.607 23.593,5.029 24.355,5.029 24.355,2.607 25.117,2.607 25.117,5.029 25.879,5.029 25.879,2.607 26.641,2.607 26.641,5.029 27.403,5.029 27.403,2.607 28.165,2.607 28.165,5.029 28.927,5.029 28.927,2.607 29.689,2.607 29.689,5.029 30.451,5.029 30.451,2.607 31.213,2.607 31.213,5.029 31.975,5.029 31.975,2.607 32.737,2.607 32.737,5.029 33.499,5.029 33.499,2.607 34.261,2.607 34.261,5.029 35.023,5.029 35.023,2.607 35.785,2.607 35.785,5.029 36.547,5.029 36.547,2.607 37.309,2.607 37.309,5.029 38.071,5.029 38.071,2.607 38.833,2.607 38.833,5.029 39.595,5.029 39.595,2.607 40.357,2.607 40.357,5.029 41.119,5.029 41.119,2.607 41.881,2.607 41.881,4 42.75,4 v1(49,4)
Top_Layer_Diff_N: R5.2 R6.1 | length 100.9
  Top Layer w0.381: R5.2 5.11,21.26 5.11,21.459 5.333,21.682 6.341,21.682 8.373,21.682 cw(c8.373,21.238) 8.818,21.238 8.818,21.063 ccw(c9.897,21.063) 10.977,21.063 10.977,22.593 cw(c11.421,22.593) 11.866,22.593 11.866,21.063 ccw(c12.945,21.063) 14.025,21.063 14.025,22.593 cw(c14.469,22.593) 14.914,22.593 14.914,21.063 ccw(c15.993,21.063) 17.073,21.063 17.073,22.593 cw(c17.517,22.593) 17.962,22.593 17.962,21.063 ccw(c19.041,21.063) 20.121,21.063 20.121,22.593 cw(c20.565,22.593) 21.01,22.593 21.01,21.063 ccw(c22.089,21.063) 23.169,21.063 23.169,22.593 cw(c23.613,22.593) 24.058,22.593 24.058,21.063 ccw(c25.137,21.063) 26.217,21.063 26.217,22.593 cw(c26.661,22.593) 27.106,22.593 27.106,21.063 ccw(c28.185,21.063) 29.265,21.063 29.265,22.593 cw(c29.709,22.593) 30.154,22.593 30.154,21.063 ccw(c31.233,21.063) 32.313,21.063 32.313,22.593 cw(c32.757,22.593) 33.202,22.593 33.202,21.063 ccw(c34.281,21.063) 35.361,21.063 35.361,22.593 cw(c35.805,22.593) 36.25,22.593 36.25,21.063 ccw(c37.329,21.063) 38.409,21.063 38.409,22.593 cw(c38.853,22.593) 39.298,22.593 39.298,21.063 ccw(c40.377,21.063) 41.457,21.063 41.457,22.593 cw(c41.901,22.593) 42.346,22.593 42.346,21.063 ccw(c43.425,21.063) 44.505,21.063 44.505,21.238 cw(c44.949,21.238) 44.949,21.682 47.75,21.682 49.518,21.683 50.15,21.05 R6.1
Top_Layer_Diff_P: R3.2 R4.1 | length 100.9
  Top Layer w0.381: R3.2 5.11,22.74 5.11,22.541 5.333,22.317 6.341,22.317 8.373,22.317 cw(c8.373,21.238) 9.453,21.238 9.453,21.063 ccw(c9.897,21.063) 10.342,21.063 10.342,22.593 cw(c11.421,22.593) 12.501,22.593 12.501,21.063 ccw(c12.945,21.063) 13.39,21.063 13.39,22.593 cw(c14.469,22.593) 15.549,22.593 15.549,21.063 ccw(c15.993,21.063) 16.438,21.063 16.438,22.593 cw(c17.517,22.593) 18.597,22.593 18.597,21.063 ccw(c19.041,21.063) 19.486,21.063 19.486,22.593 cw(c20.565,22.593) 21.645,22.593 21.645,21.063 ccw(c22.089,21.063) 22.534,21.063 22.534,22.593 cw(c23.613,22.593) 24.693,22.593 24.693,21.063 ccw(c25.137,21.063) 25.582,21.063 25.582,22.593 cw(c26.661,22.593) 27.741,22.593 27.741,21.063 ccw(c28.185,21.063) 28.63,21.063 28.63,22.593 cw(c29.709,22.593) 30.789,22.593 30.789,21.063 ccw(c31.233,21.063) 31.678,21.063 31.678,22.593 cw(c32.757,22.593) 33.837,22.593 33.837,21.063 ccw(c34.281,21.063) 34.726,21.063 34.726,22.593 cw(c35.805,22.593) 36.885,22.593 36.885,21.063 ccw(c37.329,21.063) 37.774,21.063 37.774,22.593 cw(c38.853,22.593) 39.933,22.593 39.933,21.063 ccw(c40.377,21.063) 40.822,21.063 40.822,22.593 cw(c41.901,22.593) 42.981,22.593 42.981,21.063 ccw(c43.425,21.063) 43.87,21.063 43.87,21.238 cw(c44.949,21.238) 44.949,22.317 47.487,22.317 47.75,22.318 49.518,22.318 50.15,22.95 R4.1
Top_Layer_Single: R1.2 R2.1 | length 126.7
  Top Layer w0.254: R1.2 7,28 7.127,28 ccw(c7.127,28.381) 7.508,28.381 7.508,28.52 cw(c7.889,28.52) 8.27,28.52 8.27,27.412 ccw(c8.651,27.412) 9.032,27.412 9.032,28.52 cw(c9.413,28.52) 9.794,28.52 9.794,27.412 ccw(c10.175,27.412) 10.556,27.412 10.556,28.52 cw(c10.937,28.52) 11.318,28.52 11.318,27.412 ccw(c11.699,27.412) 12.08,27.412 12.08,28.52 cw(c12.461,28.52) 12.842,28.52 12.842,27.412 ccw(c13.223,27.412) 13.604,27.412 13.604,28.52 cw(c13.985,28.52) 14.366,28.52 14.366,27.412 ccw(c14.747,27.412) 15.128,27.412 15.128,28.52 cw(c15.509,28.52) 15.89,28.52 15.89,27.412 ccw(c16.271,27.412) 16.652,27.412 16.652,28.52 cw(c17.033,28.52) 17.414,28.52 17.414,27.412 ccw(c17.795,27.412) 18.176,27.412 18.176,28.52 cw(c18.557,28.52) 18.938,28.52 18.938,27.412 ccw(c19.319,27.412) 19.7,27.412 19.7,28.52 cw(c20.081,28.52) 20.462,28.52 20.462,27.412 ccw(c20.843,27.412) 21.224,27.412 21.224,28.52 cw(c21.605,28.52) 21.986,28.52 21.986,27.412 ccw(c22.367,27.412) 22.748,27.412 22.748,28.52 cw(c23.129,28.52) 23.51,28.52 23.51,27.412 ccw(c23.891,27.412) 24.272,27.412 24.272,28.52 cw(c24.653,28.52) 25.034,28.52 25.034,27.412 ccw(c25.415,27.412) 25.796,27.412 25.796,28.52 cw(c26.177,28.52) 26.558,28.52 26.558,27.412 ccw(c26.939,27.412) 27.32,27.412 27.32,28.52 cw(c27.701,28.52) 28.082,28.52 28.082,27.412 ccw(c28.463,27.412) 28.844,27.412 28.844,28.52 cw(c29.225,28.52) 29.606,28.52 29.606,27.412 ccw(c29.987,27.412) 30.368,27.412 30.368,28.52 cw(c30.749,28.52) 31.13,28.52 31.13,27.412 ccw(c31.511,27.412) 31.892,27.412 31.892,28.52 cw(c32.273,28.52) 32.654,28.52 32.654,27.412 ccw(c33.035,27.412) 33.416,27.412 33.416,28.52 cw(c33.797,28.52) 34.178,28.52 34.178,27.412 ccw(c34.559,27.412) 34.94,27.412 34.94,28.52 cw(c35.321,28.52) 35.702,28.52 35.702,27.412 ccw(c36.083,27.412) 36.464,27.412 36.464,28.52 cw(c36.845,28.52) 37.226,28.52 37.226,27.412 ccw(c37.607,27.412) 37.988,27.412 37.988,28.52 cw(c38.369,28.52) 38.75,28.52 38.75,27.412 ccw(c39.131,27.412) 39.512,27.412 39.512,28.52 cw(c39.893,28.52) 40.274,28.52 40.274,27.412 ccw(c40.655,27.412) 41.036,27.412 41.036,28.52 cw(c41.417,28.52) 41.798,28.52 41.798,27.412 ccw(c42.179,27.412) 42.56,27.412 42.56,28.52 cw(c42.941,28.52) 43.322,28.52 43.322,27.412 ccw(c43.703,27.412) 44.084,27.412 44.084,28.52 cw(c44.465,28.52) 44.846,28.52 44.846,27.412 ccw(c45.227,27.412) 45.608,27.412 45.608,28.52 cw(c45.989,28.52) 46.37,28.52 46.37,27.412 ccw(c46.751,27.412) 47.132,27.412 47.132,28.52 cw(c47.513,28.52) 47.894,28.52 47.894,28.381 ccw(c48.275,28.381) 48.275,28 49,28 R2.1
VCC: R1.1 R3.1 R5.1 R7.1 R9.1 R11.1 R13.1 R15.1 R17.1 R19.1 R21.1 R23.1 | length 44.8
  Top Layer w0.254: R1.1 R3.1 R5.1 R7.1 R9.1 R11.1 R13.1 R15.1 R17.1 R19.1 R21.1 R23.1 3.2,-15.05 3.2,-16.7 v1(3.25,-16.75)

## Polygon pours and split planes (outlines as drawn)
VCC on Bottom Layer "VCC_L06_P001" (solid, remove dead copper, pour order 1): 55,-20 55,32 0,32 0,-20
GND on Top Layer "GND_L01_P000" (solid, remove dead copper, pour order 0): 0,32 55,32 55,-20 0,-20
GND on Int1 (GND) (split plane): 54.49,-19.49 0.51,-19.49 0.51,31.49 54.49,31.49
VCC on Int4 (PWR) (split plane): 54.49,-19.49 0.51,-19.49 0.51,31.49 54.49,31.49

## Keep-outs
Keep-Out Layer:
  the board outline again, w0.2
